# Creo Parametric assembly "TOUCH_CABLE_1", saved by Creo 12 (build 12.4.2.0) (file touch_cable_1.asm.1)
Units: Custom; MM, KILOGRAM, SECS

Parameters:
  PTC_WM_ITERATION = "0"
  PTC_WM_VERSION = "-.0"
  PTC_WM_LIFECYCLE_STATE = "In Work"
  PTC_WM_LIFECYCLE = "MO_CADDocument"
  PTC_WM_CREATED_BY = "Maximilian Roepper (Z0017RMS: MO)"
  PTC_WM_CREATED_ON = "18-Sep-26 11:36:42 AM"
  PTC_WM_MODIFIED_BY = "Maximilian Roepper (Z0017RMS: MO)"
  PTC_WM_MODIFIED_ON = "18-Sep-26 11:36:46 AM"
  PDMLINKNUMBER = "PDM000071455138"
  PTC_WM_NAME = "touch_cable_1.asm"
  PTC_WM_NUMBER = "PDM000071455138"

Other parameters: WEIGHT, WEIGHT_FACTOR, WEIGHT_ADD, MC_ERRORS, SUPPLIER, ISPOSITIONINGASSEMBLY

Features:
  1. coordinate system
  2. imported feature
  3. component "TOUCH_CABLE_CONTACTS_1"
  4. component "TOUCH_CABLE_FILM_1"

Other named items: DRW_VIEW_ORG, ROUGH-GROB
